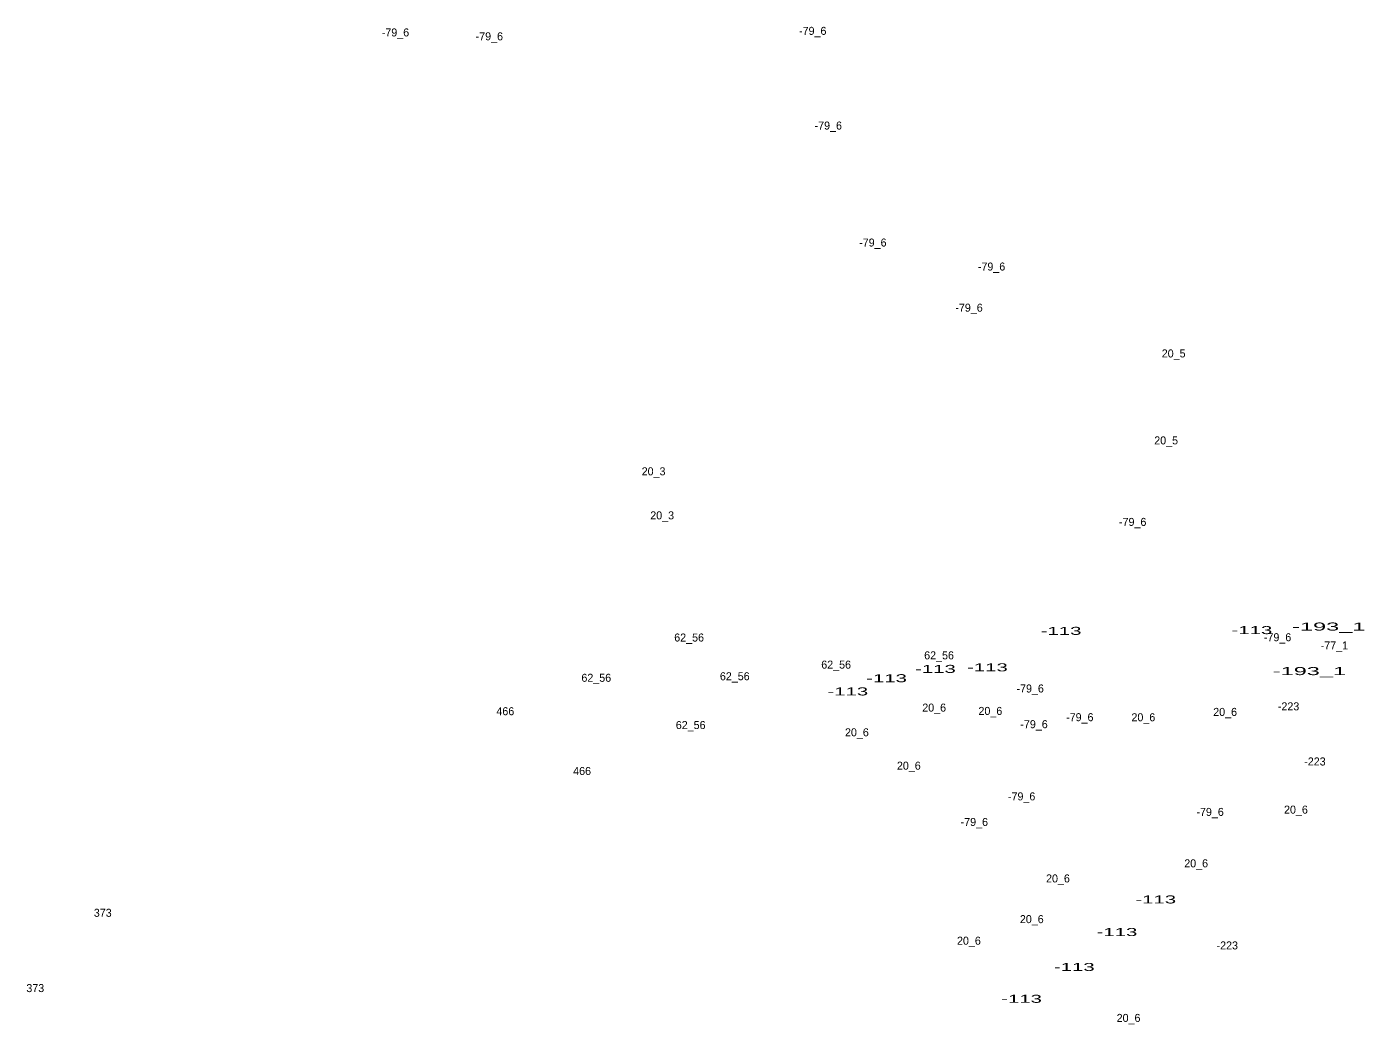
# Model space of a CAD drawing. Extents: x -661742 to -657295, y -1002932 to -996888.
# Drawn here: x -659898 to -659229, y -998363 to -997865 of the extents above; entities that cross this region are included whole.
import ezdxf
from ezdxf.enums import TextEntityAlignment as Align

# ---------------------------------------------------------------- set-up
doc = ezdxf.new("R2010")
doc.units = 0
doc.header["$LTSCALE"] = 1.6
doc.layers.add('24', color=7, linetype='Continuous')

msp = doc.modelspace()

# ---------------------------------------------------------------- texts
at = {"layer": '24'}
for s, p in [('-79_6', (-659713.518, -997869.61)), ('-79_6', (-659504.918, -997868.84)), ('-79_6', (-659666.598, -997871.55)), ('-79_6', (-659497.158, -997916.16)), ('-79_6', (-659474.868, -997974.61)), ('-79_6', (-659415.538, -997986.6)), ('-79_6', (-659426.788, -998007.16)), ('20_5', (-659324.499, -998030.02)), ('20_5', (-659328.259, -998073.48)), ('20_3', (-659584.479, -998088.94)), ('20_3', (-659580.189, -998110.94)), ('-79_6', (-659344.978, -998114.21)), ('62_56', (-659566.716, -998171.99)), ('-79_6', (-659272.548, -998171.85)), ('-77_1', (-659244.157, -998175.95)), ('62_56', (-659441.776, -998180.89)), ('62_56', (-659493.226, -998185.53)), ('62_56', (-659613.126, -998192.11)), ('62_56', (-659543.896, -998191.34)), ('-79_6', (-659396.228, -998197.45)), ('466', (-659658.593, -998208.82)), ('20_6', (-659444.224, -998207.01)), ('20_6', (-659416.124, -998208.67)), ('20_6', (-659298.774, -998209.16)), ('-223', (-659267.065, -998206.38)), ('62_56', (-659565.936, -998215.72)), ('-79_6', (-659394.298, -998215.3)), ('-79_6', (-659371.418, -998211.81)), ('20_6', (-659339.644, -998211.84)), ('20_6', (-659482.844, -998219.35)), ('20_6', (-659456.884, -998236.03)), ('-223', (-659253.885, -998233.92)), ('466', (-659620.213, -998238.69)), ('-79_6', (-659400.498, -998251.37)), ('-79_6', (-659424.148, -998264.17)), ('-79_6', (-659306.278, -998259.13)), ('20_6', (-659263.374, -998257.99)), ('20_6', (-659313.254, -998284.82)), ('20_6', (-659382.334, -998292.37)), ('373', (-659859.843, -998309.54)), ('20_6', (-659395.424, -998312.71)), ('20_6', (-659426.854, -998323.49)), ('-223', (-659297.695, -998325.85)), ('373', (-659893.573, -998347.17)), ('20_6', (-659347.044, -998362.08))]:
    msp.add_text(s, height=4, dxfattribs=at).set_placement(p, align=Align.CENTER)
for s, width, p in [('-113', 1.9, (-659380.767, -998168.66)), ('-113', 1.9, (-659285.377, -998168.27)), ('-193_1', 2.2, (-659246.973, -998166.51)), ('-113', 1.9, (-659443.577, -998187.67)), ('-113', 1.9, (-659417.597, -998186.89)), ('-193_1', 2.2, (-659256.643, -998188.76)), ('-113', 1.9, (-659468.007, -998192.32)), ('-113', 1.9, (-659487.387, -998198.92)), ('-113', 1.9, (-659333.457, -998302.87)), ('-113', 1.9, (-659352.847, -998319.16)), ('-113', 1.9, (-659374.177, -998336.61)), ('-113', 1.9, (-659400.537, -998352.52))]:
    msp.add_text(s, height=4, dxfattribs=dict(at, width=width)).set_placement(p, align=Align.CENTER)

doc.saveas('drawing.dxf')
